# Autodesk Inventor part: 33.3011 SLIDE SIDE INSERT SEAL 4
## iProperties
Created: 2007-06
Part Number: 33.3011 SLIDE SIDE INSERT SEAL 4
Material: Rubber
Document SubType Name: Modeling
Designer: Andy Moles
Density: 0.93 g/cm^3
Author: Andy Moles
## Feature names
1. Extrusion1
